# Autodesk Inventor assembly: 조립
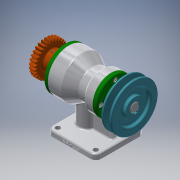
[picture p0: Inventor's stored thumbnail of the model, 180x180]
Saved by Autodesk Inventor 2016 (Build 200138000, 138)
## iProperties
Created: 2019-01
Part Number: 조립
Material: 일반
Document SubType Name: Assembly
Designer: USER
Author: USER
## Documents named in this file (15)
- C:\Users\USER\Desktop\490107V1008\조립.iam
- C:\Users\USER\Desktop\490107V1008\본체.ipt
- C:\Users\USER\Desktop\490107V1008\V-벨트풀리.ipt
- C:\Users\USER\Desktop\490107V1008\뒤커버.ipt
- C:\Users\USER\Desktop\490107V1008\멈춤나사 M3.ipt
- C:\Users\USER\Desktop\490107V1008\베어링 6203.ipt
- C:\Users\USER\Desktop\490107V1008\베어링 6205.ipt
- C:\Users\USER\Desktop\490107V1008\볼트 M4.ipt
- C:\Users\USER\Desktop\490107V1008\스퍼기어.ipt
- C:\Users\USER\Desktop\490107V1008\앞커버.ipt
- C:\Users\USER\Desktop\490107V1008\오일 실 17 30 8.ipt
- C:\Users\USER\Desktop\490107V1008\오일 실 25 38 8.ipt
- C:\Users\USER\Desktop\490107V1008\축.ipt
- C:\Users\USER\Desktop\490107V1008\키 5 x 5 x 20.ipt
- C:\Users\USER\Desktop\490107V1008\키 6 x 6 x 18.ipt
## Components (1 placed, 1 different names)
1. V-벨트풀리:1
